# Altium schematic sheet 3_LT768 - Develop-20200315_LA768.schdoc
size 800 x 261 mm
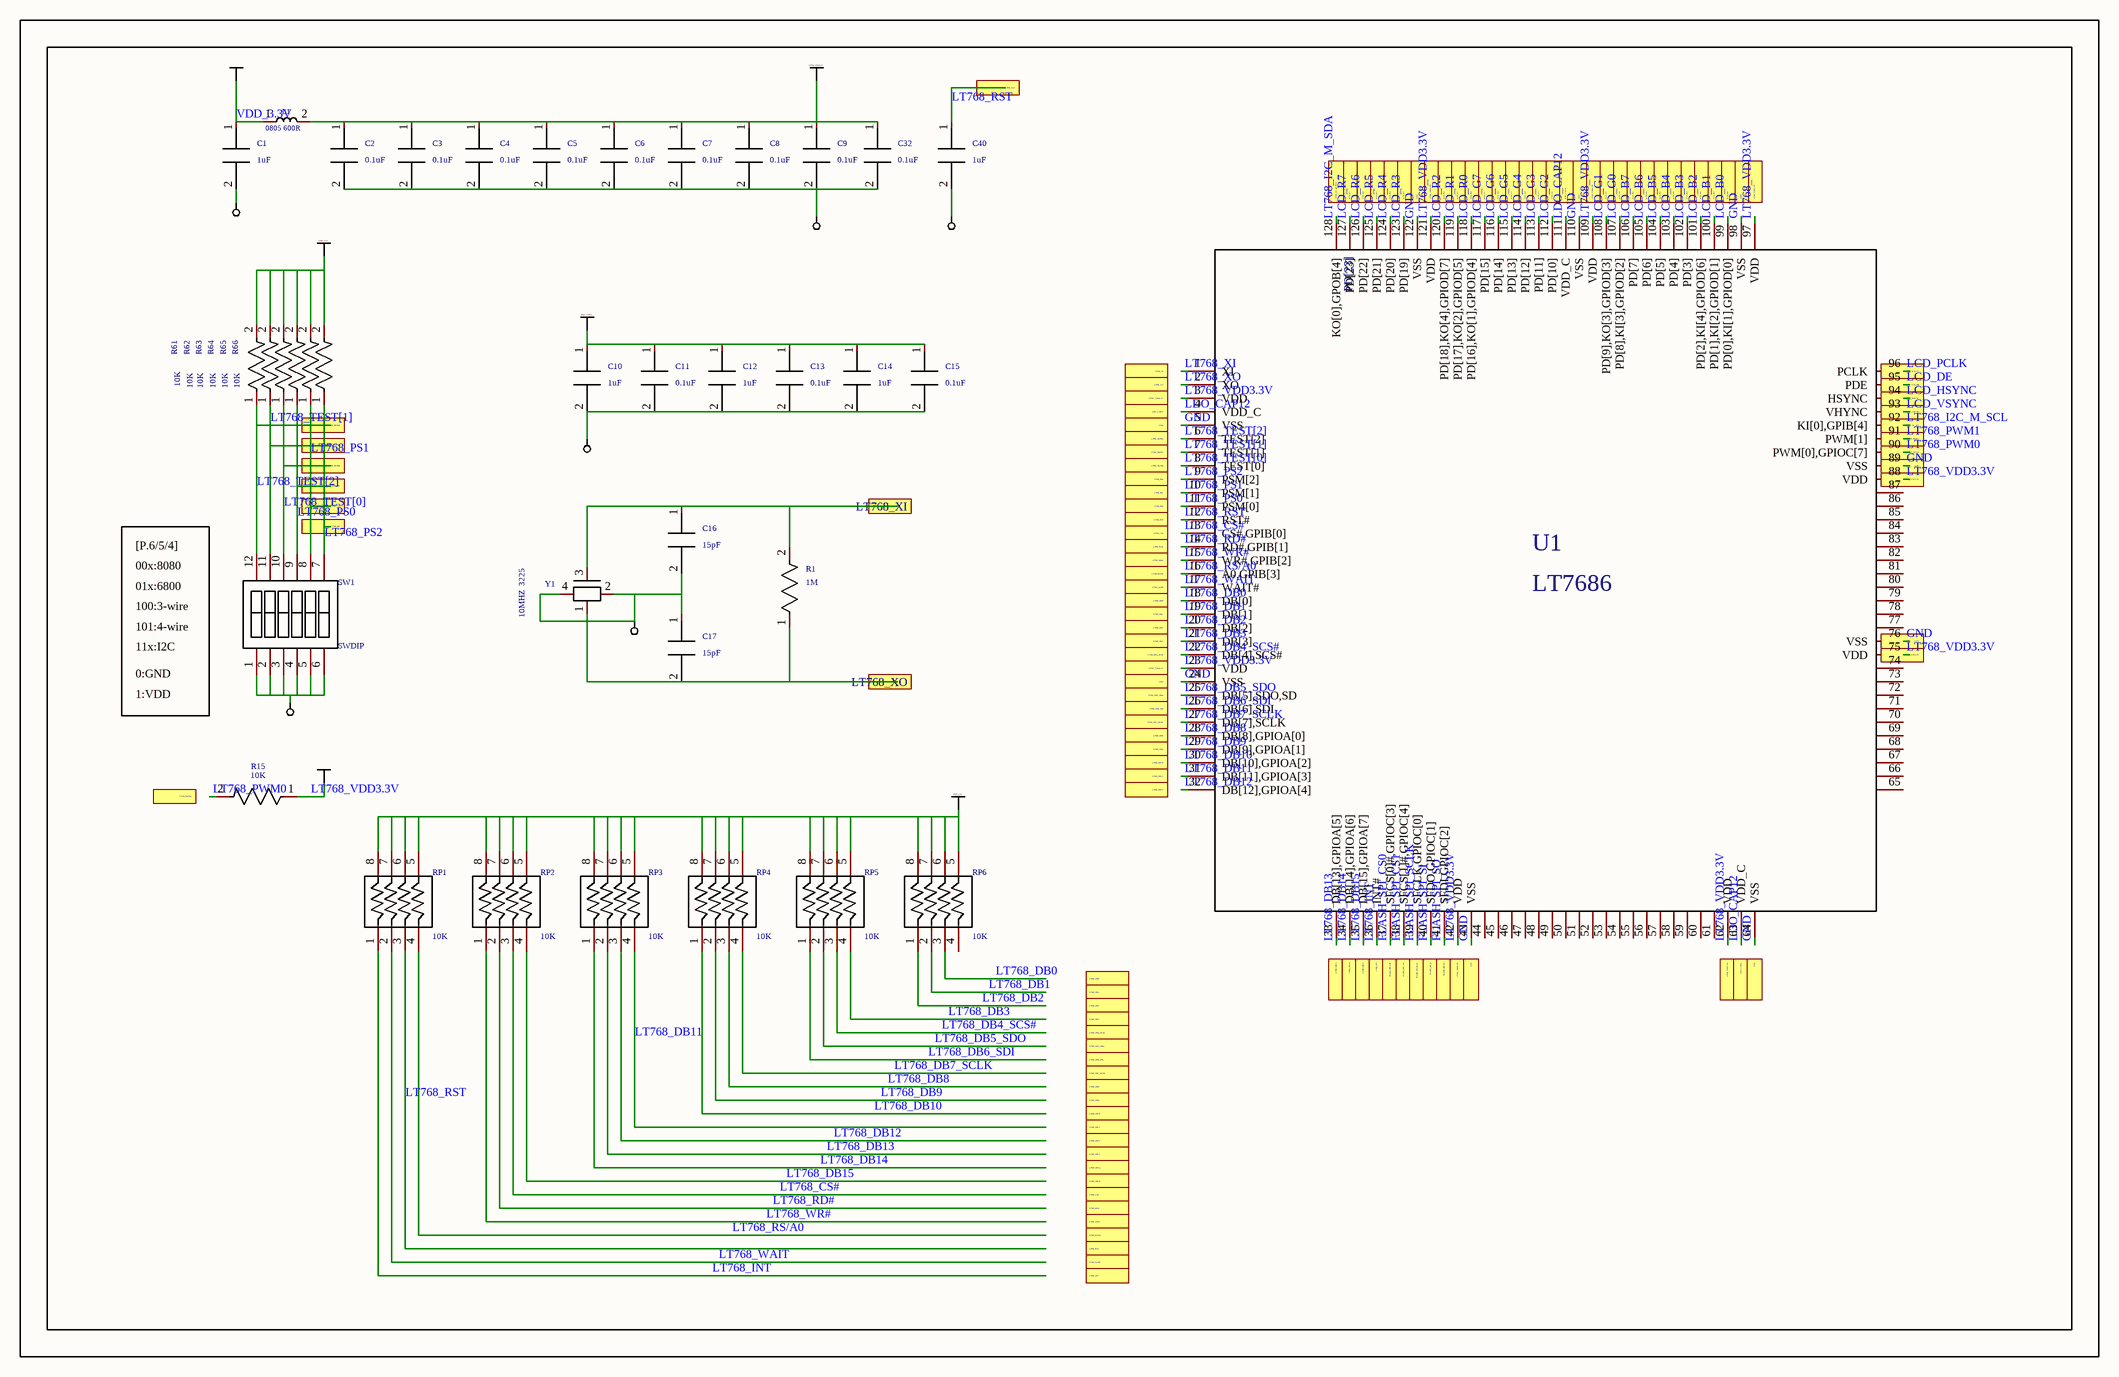
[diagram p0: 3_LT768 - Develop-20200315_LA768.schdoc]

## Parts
C1  1uF
C2  0.1uF
C3  0.1uF
C4  0.1uF
C5  0.1uF
C6  0.1uF
C7  0.1uF
C8  0.1uF
C9  0.1uF
C10  1uF
C11  0.1uF
C12  1uF
C13  0.1uF
C14  1uF
C15  0.1uF
C16  15pF
C17  15pF
C32  0.1uF
C40  1uF
L1  0805 600R
R1  1M
R15  10K
R61  10K
R62  10K
R63  10K
R64  10K
R65  10K
R66  10K
RP1  10K
RP2  10K
RP3  10K
RP4  10K
RP5  10K
RP6  10K
SW1  SWDIP
U1  OldName: LT7686  NAME: PD[23]  (hidden comment: LT768-136)
Y1  10MHZ  3225  [CRYSTAL-3225]

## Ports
FLASH_SPI_CS0 (in), FLASH_SPI_CS1 (in), FLASH_SPI_SCLK (in), FLASH_SPI_SI (in), FLASH_SPI_SO (in), GND (in), LCD_B0 (in), LCD_B1 (in), LCD_B2 (in), LCD_B3 (in), LCD_B4 (in), LCD_B5 (in), LCD_B6 (in), LCD_B7 (in), LCD_DE (in), LCD_G0 (in), LCD_G1 (in), LCD_G2 (in), LCD_G3 (in), LCD_G4 (in), LCD_G5 (in), LCD_G6 (in), LCD_G7 (in), LCD_HSYNC (in), LCD_PCLK (in), LCD_R0 (in), LCD_R1 (in), LCD_R2 (in), LCD_R3 (in), LCD_R4 (in), LCD_R5 (in), LCD_R6 (in), LCD_R7 (in), LCD_VSYNC (in), LDO_CAP12 (in), LT768_CS# (in), LT768_CS# (out), LT768_DB0 (in), LT768_DB0 (out), LT768_DB1 (in), LT768_DB1 (out), LT768_DB2 (in), LT768_DB2 (out), LT768_DB3 (in), LT768_DB3 (out), LT768_DB4_SCS# (in), LT768_DB4_SCS# (out), LT768_DB5_SDO (in), LT768_DB5_SDO (out), LT768_DB6_SDI (in), LT768_DB6_SDI (out), LT768_DB7_SCLK (in), LT768_DB7_SCLK (out), LT768_DB8 (in), LT768_DB8 (out), LT768_DB9 (in), LT768_DB9 (out), LT768_DB10 (in), LT768_DB10 (out), LT768_DB11 (in), LT768_DB11 (out), LT768_DB12 (in), LT768_DB12 (out), LT768_DB13 (in), LT768_DB13 (out), LT768_DB14 (in), LT768_DB14 (out), LT768_DB15 (in), LT768_DB15 (out), LT768_I2C_M_SCL (in), LT768_I2C_M_SDA (in), LT768_INT (in), LT768_INT (out), LT768_PS0 (in), LT768_PS1 (in), LT768_PS2 (in), LT768_PWM0 (in), LT768_PWM1 (in), LT768_RD# (in), LT768_RD# (out), LT768_RS/A0 (in), LT768_RS/A0 (out), LT768_RST (in), LT768_RST (out), LT768_TEST[0] (in), LT768_TEST[1] (in), LT768_TEST[2] (in), LT768_VDD3.3V (in), LT768_WAIT (in), LT768_WAIT (out), LT768_WR# (in), LT768_WR# (out), LT768_XI (in), LT768_XO (in)

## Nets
GND: C1.2 C2.2 C3.2 C4.2 C5.2 C6.2 C7.2 C8.2 C9.2 C10.2 C11.2 C12.2 C13.2 C14.2 C15.2 C16.2 C17.1 C32.2 C40.2 SW1.1 SW1.2 SW1.3 SW1.4 SW1.5 SW1.6 U1.5(VSS) U1.24(VSS) U1.43(VSS) U1.64(VSS) U1.76(VSS) U1.89(VSS) U1.98(VSS) U1.110(VSS) U1.122(VSS) Y1.2 Y1.4
LDO_CAP12: C10.1 C11.1 C12.1 C13.1 C14.1 C15.1 U1.4(VDD_C) U1.63(VDD_C) U1.111(VDD_C)
LT768_VDD3.3V: C2.1 C3.1 C4.1 C5.1 C6.1 C7.1 C8.1 C9.1 C32.1 L1.2 R15.1 U1.3(VDD) U1.23(VDD) U1.42(VDD) U1.62(VDD) U1.75(VDD) U1.88(VDD) U1.97(VDD) U1.109(VDD) U1.121(VDD)
VDD_3.3V: C1.1 L1.1 R61.2 R62.2 R63.2 R64.2 R65.2 R66.2 RP1.5 RP1.6 RP1.7 RP1.8 RP2.5 RP2.6 RP2.7 RP2.8 RP3.5 RP3.6 RP3.7 RP3.8 RP4.5 RP4.6 RP4.7 RP4.8 RP5.5 RP5.6 RP5.7 RP5.8 RP6.5 RP6.6 RP6.7 RP6.8
FLASH_SPI_CS0: U1.37(SFCS[0]#,GPIOC[3])
FLASH_SPI_CS1: U1.38(SFCS[1]#,GPIOC[4])
FLASH_SPI_SCLK: U1.39(SFCLK,GPIOC[0])
FLASH_SPI_SI: U1.40(SFDO,GPIOC[1])
FLASH_SPI_SO: U1.41(SFDI,GPIOC[2])
LCD_B0: U1.99(PD[0],KI[1],GPIOD[0])
LCD_B1: U1.100(PD[1],KI[2],GPIOD[1])
LCD_B2: U1.101(PD[2],KI[4],GPIOD[6])
LCD_B3: U1.102(PD[3])
LCD_B4: U1.103(PD[4])
LCD_B5: U1.104(PD[5])
LCD_B6: U1.105(PD[6])
LCD_B7: U1.106(PD[7])
LCD_DE: U1.95(PDE)
LCD_G0: U1.107(PD[8],KI[3],GPIOD[2])
LCD_G1: U1.108(PD[9],KO[3],GPIOD[3])
LCD_G2: U1.112(PD[10])
LCD_G3: U1.113(PD[11])
LCD_G4: U1.114(PD[12])
LCD_G5: U1.115(PD[13])
LCD_G6: U1.116(PD[14])
LCD_G7: U1.117(PD[15])
LCD_HSYNC: U1.94(HSYNC)
LCD_PCLK: U1.96(PCLK)
LCD_R0: U1.118(PD[16],KO[1],GPIOD[4])
LCD_R1: U1.119(PD[17],KO[2],GPIOD[5])
LCD_R2: U1.120(PD[18],KO[4],GPIOD[7])
LCD_R3: U1.123(PD[19])
LCD_R4: U1.124(PD[20])
LCD_R5: U1.125(PD[21])
LCD_R6: U1.126(PD[22])
LCD_R7: U1.127(PD[23])
LCD_VSYNC: U1.93(VHYNC)
LT768_CS#: RP2.3 U1.13(CS#,GPIB[0])
LT768_DB0: RP6.3 U1.18(DB[0])
LT768_DB1: RP6.2 U1.19(DB[1])
LT768_DB2: RP6.1 U1.20(DB[2])
LT768_DB3: RP5.4 U1.21(DB[3])
LT768_DB4_SCS#: RP5.3 U1.22(DB[4],SCS#)
LT768_DB5_SDO: RP5.2 U1.25(DB[5],SDO,SD)
LT768_DB6_SDI: RP5.1 U1.26(DB[6],SDI)
LT768_DB7_SCLK: RP4.4 U1.27(DB[7],SCLK)
LT768_DB8: RP4.3 U1.28(DB[8],GPIOA[0])
LT768_DB9: RP4.2 U1.29(DB[9],GPIOA[1])
LT768_DB10: RP4.1 U1.30(DB[10],GPIOA[2])
LT768_DB11: RP3.4 U1.31(DB[11],GPIOA[3])
LT768_DB12: RP3.3 U1.32(DB[12],GPIOA[4])
LT768_DB13: RP3.2 U1.33(DB[13],GPIOA[5])
LT768_DB14: RP3.1 U1.34(DB[14],GPIOA[6])
LT768_DB15: RP2.4 U1.35(DB[15],GPIOA[7])
LT768_I2C_M_SCL: U1.92(KI[0],GPIB[4])
LT768_I2C_M_SDA: U1.128(KO[0],GPOB[4])
LT768_INT: RP1.1 U1.36(INT#)
LT768_PS0: R64.1 SW1.9 U1.11(PSM[0]) ; port LT768_PS0
LT768_PS1: R65.1 SW1.8 U1.10(PSM[1])
LT768_PS2: R66.1 SW1.7 U1.9(PSM[2])
LT768_PWM0: R15.2 U1.90(PWM[0],GPIOC[7])
LT768_PWM1: U1.91(PWM[1])
LT768_RD#: RP2.2 U1.14(RD#,GPIB[1])
LT768_RS/A0: RP1.4 U1.16(A0,GPIB[3])
LT768_RST: C40.1 RP1.3 U1.12(RST#) ; port LT768_RST
LT768_TEST[0]: R63.1 SW1.10 U1.8(TEST[0]) ; port LT768_TEST[0]
LT768_TEST[1]: R61.1 R62.1 SW1.11 SW1.12 U1.6(TEST[2]) U1.7(TEST[1]) ; port LT768_TEST[2], port LT768_TEST[1]  [also labelled LT768_TEST[2]]
LT768_WAIT: RP1.2 U1.17(WAIT#)
LT768_WR#: RP2.1 U1.15(WR#,GPIB[2])
LT768_XI: C16.1 R1.2 Y1.3 ; port LT768_XI
LT768_XI: U1.1(XI)  [a separate net that carries the same name]
LT768_XO: C17.2 R1.1 Y1.1 ; port LT768_XO
LT768_XO: U1.2(XO)  [a separate net that carries the same name]

Not connected (* = marked no-connect by the designer): RP6 4; U1 44(NC) 45(NC) 46(NC) 47(NC) 48(NC) 49(NC) 50(NC) 51(NC) 52(NC) 53(NC) 54(NC) 55(NC) 56(NC) 57(NC) 58(NC) 59(NC) 60(NC) 61(NC) 65(NC) 66(NC) 67(NC) 68(NC) 69(NC) 70(NC) 71(NC) 72(NC) 73(NC) 74(NC) 77(NC) 78(NC) 79(NC) 80(NC) 81(NC) 82(NC) 83(NC) 84(NC) 85(NC) 86(NC) 87(NC)

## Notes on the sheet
- [P.6/5/4]
- 00x:8080
- 01x:6800
- 100:3-wire
- 101:4-wire
- 11x:I2C
- 0:GND
- 1:VDD

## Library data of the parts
C1-C17 C32 C40 = CAP0603: Capacitor; PART DESC: CERAMIC CAP.0.1UF/50V +/-20% 0603; PART NO: 014104BZ2503; PART NUMBER: 022-109600310-00; Symbol: CAP; Add into BOM: yes; _: 0.0103; PCB DECAL: C0603
L1 = 47UH-CHOKE: BEAD; PART DESC: COIL 47uH-CHOKE; PART NUMBER: 037-001000001-00; Symbol: FB220; Add into BOM: yes; PCB DECAL: L0805
R1 R15 R61-R66 = RES: Resistance; Symbol: RESZ-V; Add into BOM: yes; PCB DECAL: R0603
RP1-RP6 = RP4: Resistor Packs; Symbol: RP-4; Add into BOM: yes; PCB DECAL: 8R4R
SW1 = SWDIP: SWITCH; Symbol: SWDIP6; Add into BOM: yes; PCB DECAL: SW12
U1 = LT768-136: IC; Symbol: LQFP128; Add into BOM: yes; PCB DECAL: LQFP128L
Y1 = CRYSTAL-3225: XTAL; Manufacturer #1: FOX; Add into BOM: yes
